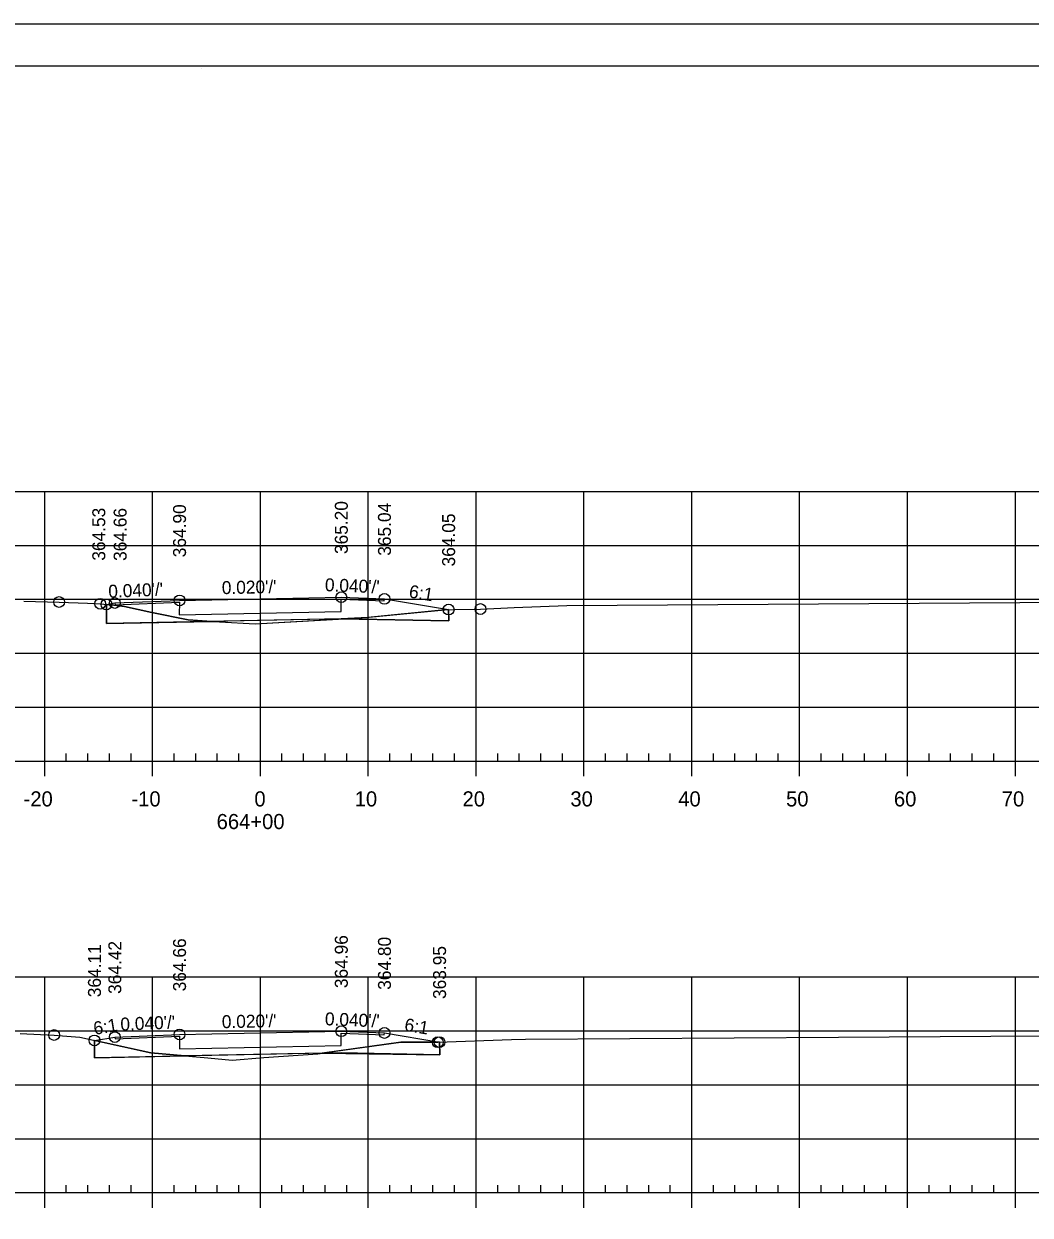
# Model space of a CAD drawing. Extents: x 1359801 to 1362404, y 372415 to 374228.
# Drawn here: x 1361798 to 1361891.3, y 373477.5 to 373588 of the extents above; entities that cross this region are included whole.
import ezdxf

# ---------------------------------------------------------------- set-up
doc = ezdxf.new("R2010")
doc.units = 0
for name, color, linetype in [('S_DRG_PT_SYM', 7, 'Continuous'), ('S_ELECTRIC_UTILITIES_ANNOT', 7, 'Continuous'), ('S_IRON_PIN', 7, 'Continuous'), ('S_MAILBOX', 7, 'Continuous'), ('S_PRIMARY_CTL', 7, 'Continuous'), ('S_SANITARY_SEWER', 7, 'Continuous'), ('S_SHOULDER', 7, 'Continuous'), ('S_UNDERGROUND_CABLE', 7, 'Continuous'), ('S_UTL_PT_SYM', 7, 'Continuous'), ('S_WATER_UTILITIES', 7, 'Continuous')]:
    doc.layers.add(name, color=color, linetype=linetype)

msp = doc.modelspace()

# ---------------------------------------------------------------- linework, layer by layer
at = {"layer": 'S_DRG_PT_SYM'}
for points in [[(1361797.95, 373534.42), (1361801.22, 373534.35), (1361803.85, 373534.24), (1361805.03, 373534.19), (1361806.05, 373534.08), (1361807.28, 373533.92), (1361809.82, 373533.39), (1361813.18, 373532.7), (1361816.09, 373532.51), (1361819.41, 373532.34), (1361829.33, 373532.9), (1361829.84, 373532.93), (1361829.96, 373532.94), (1361837, 373533.64), (1361837.92, 373533.66), (1361840.29, 373533.7), (1361843.42, 373533.83), (1361848.29, 373534.02), (1361890.3, 373534.31), (1361901.28, 373534.38)], [(1361797.62, 373494.35), (1361800.76, 373494.21), (1361801.54, 373494.14), (1361803.15, 373494), (1361804.42, 373493.72), (1361809.74, 373492.55), (1361815.01, 373492.08), (1361817.26, 373491.89), (1361820.2, 373492.11), (1361825.21, 373492.47), (1361826.85, 373492.7), (1361832.9, 373493.55), (1361835.05, 373493.54), (1361836.33, 373493.54), (1361843.17, 373493.79), (1361844.46, 373493.84), (1361873.48, 373494.02), (1361897.03, 373494.17)]]:
    msp.add_lwpolyline(points, dxfattribs=at)
at = {"layer": 'S_ELECTRIC_UTILITIES_ANNOT'}
for p, q in [((1361805.61, 373534.13), (1361805.61, 373532.36)), ((1361837.35, 373532.6), (1361837.34, 373533.65)), ((1361813.18, 373532.7), (1361809.82, 373533.39)), ((1361815.35, 373532.56), (1361815.35, 373532.56)), ((1361815.35, 373532.56), (1361815.35, 373532.56)), ((1361804.5, 373493.71), (1361804.5, 373492.1)), ((1361836.53, 373492.38), (1361836.5, 373493.55)), ((1361804.5, 373492.1), (1361812.88, 373492.27)), ((1361825.61, 373492.53), (1361836.53, 373492.38)), ((1361825.61, 373492.53), (1361825.61, 373492.53))]:
    msp.add_line(p, q, dxfattribs=at)
for points in [[(1361809.82, 373533.39), (1361807.28, 373533.92), (1361806.05, 373534.08), (1361805.61, 373534.13)], [(1361837.34, 373533.65), (1361837, 373533.64), (1361829.84, 373532.93)], [(1361805.61, 373532.36), (1361815.35, 373532.56), (1361813.18, 373532.7)], [(1361815.35, 373532.56), (1361815.35, 373532.56), (1361816.09, 373532.51), (1361819.41, 373532.34), (1361827.51, 373532.8), (1361827.51, 373532.8), (1361815.35, 373532.56)], [(1361829.84, 373532.93), (1361827.39, 373532.8), (1361837.35, 373532.6)], [(1361812.88, 373492.27), (1361809.74, 373492.55), (1361804.5, 373493.71)], [(1361836.5, 373493.55), (1361836.33, 373493.54), (1361835.05, 373493.54), (1361832.9, 373493.55), (1361825.61, 373492.53)], [(1361825.61, 373492.53), (1361812.88, 373492.27), (1361812.88, 373492.27)], [(1361812.88, 373492.27), (1361812.88, 373492.27), (1361815.01, 373492.08), (1361817.26, 373491.89), (1361820.2, 373492.11), (1361825.21, 373492.47), (1361825.61, 373492.53), (1361825.61, 373492.53)]]:
    msp.add_lwpolyline(points, dxfattribs=at)
at = {"layer": 'S_MAILBOX'}
for p, q in [((1361674.89, 373544.6), (1361964.89, 373544.6)), ((1361799.89, 373519.6), (1361799.89, 373544.6)), ((1361809.89, 373519.6), (1361809.89, 373544.6)), ((1361819.89, 373519.6), (1361819.89, 373544.6)), ((1361829.89, 373519.6), (1361829.89, 373544.6)), ((1361839.89, 373519.6), (1361839.89, 373544.6)), ((1361849.89, 373519.6), (1361849.89, 373544.6)), ((1361859.89, 373519.6), (1361859.89, 373544.6)), ((1361869.89, 373519.6), (1361869.89, 373544.6)), ((1361879.89, 373519.6), (1361879.89, 373544.6)), ((1361889.89, 373519.6), (1361889.89, 373544.6)), ((1361674.89, 373539.6), (1361964.89, 373539.6)), ((1361674.89, 373534.6), (1361964.89, 373534.6)), ((1361674.89, 373529.6), (1361964.89, 373529.6)), ((1361674.89, 373524.6), (1361964.89, 373524.6)), ((1361674.89, 373519.6), (1361964.89, 373519.6)), ((1361674.89, 373499.6), (1361964.89, 373499.6)), ((1361799.89, 373479.6), (1361799.89, 373499.6)), ((1361809.89, 373479.6), (1361809.89, 373499.6)), ((1361819.89, 373479.6), (1361819.89, 373499.6)), ((1361829.89, 373479.6), (1361829.89, 373499.6)), ((1361839.89, 373479.6), (1361839.89, 373499.6)), ((1361849.89, 373479.6), (1361849.89, 373499.6)), ((1361859.89, 373479.6), (1361859.89, 373499.6)), ((1361869.89, 373479.6), (1361869.89, 373499.6)), ((1361879.89, 373479.6), (1361879.89, 373499.6)), ((1361889.89, 373479.6), (1361889.89, 373499.6)), ((1361674.89, 373494.6), (1361964.89, 373494.6)), ((1361674.89, 373489.6), (1361964.89, 373489.6)), ((1361674.89, 373484.6), (1361964.89, 373484.6)), ((1361674.89, 373479.6), (1361964.89, 373479.6))]:
    msp.add_line(p, q, dxfattribs=at)
at = {"layer": 'S_SANITARY_SEWER'}
for points in [[(1361805.61, 373534.13), (1361806.39, 373534.26), (1361812.39, 373534.5), (1361812.39, 373534.5), (1361827.39, 373534.8), (1361831.39, 373534.64), (1361837.34, 373533.65)], [(1361804.5, 373493.71), (1361806.39, 373494.02), (1361812.39, 373494.26), (1361812.39, 373494.26), (1361827.39, 373494.56), (1361831.39, 373494.4), (1361836.5, 373493.55)]]:
    msp.add_lwpolyline(points, dxfattribs=at)
at = {"layer": 'S_SHOULDER'}
for p, q in [((1361649.49, 373587.95), (1361982.82, 373587.95)), ((1361805.61, 373532.36), (1361805.61, 373534.13)), ((1361837.34, 373533.65), (1361837.35, 373532.6)), ((1361837.35, 373532.6), (1361837.33, 373532.6)), ((1361804.5, 373492.1), (1361804.5, 373493.71)), ((1361827.39, 373492.56), (1361812.4, 373492.26)), ((1361836.53, 373492.38), (1361827.39, 373492.56)), ((1361836.5, 373493.55), (1361836.53, 373492.38)), ((1361812.4, 373492.26), (1361804.51, 373492.1))]:
    msp.add_line(p, q, dxfattribs=at)
for points in [[(1361649.48, 373587.95), (1361982.82, 373587.95), (1361982.82, 373374.61), (1361649.48, 373374.61)], [(1361895.81, 373584.06), (1361895.81, 373574.18), (1361931.54, 373574.18), (1361931.54, 373571.26), (1361954.74, 373571.26), (1361954.74, 373546.93), (1361978.07, 373546.93), (1361978.07, 373378.6), (1361661.89, 373378.6), (1361661.89, 373584.06)]]:
    msp.add_lwpolyline(points, close=True, dxfattribs=at)
for points in [[(1361812.4, 373534.33), (1361812.37, 373533.17), (1361812.37, 373533.17), (1361827.39, 373533.47), (1361827.39, 373534.63)], [(1361827.39, 373534.63), (1361831.37, 373534.47), (1361831.39, 373534.64), (1361837.34, 373533.65)], [(1361805.61, 373534.13), (1361806.39, 373534.26), (1361806.41, 373534.09), (1361812.4, 373534.33)], [(1361837.33, 373532.6), (1361827.39, 373532.8), (1361805.62, 373532.36)], [(1361804.5, 373493.71), (1361806.39, 373494.02), (1361806.41, 373493.85), (1361812.4, 373494.09)], [(1361812.4, 373494.09), (1361812.39, 373492.93), (1361827.39, 373493.23), (1361827.39, 373494.39)], [(1361827.39, 373494.39), (1361831.37, 373494.23), (1361831.39, 373494.4), (1361836.5, 373493.55)]]:
    msp.add_lwpolyline(points, dxfattribs=at)
for centre in [(1361801.22, 373534.35), (1361805.03, 373534.19), (1361805.61, 373534.13), (1361806.39, 373534.26), (1361812.39, 373534.5), (1361827.39, 373534.8), (1361831.39, 373534.64), (1361837.34, 373533.65), (1361840.29, 373533.7), (1361827.39, 373494.56), (1361831.39, 373494.4), (1361800.76, 373494.21), (1361804.5, 373493.71), (1361806.39, 373494.02), (1361812.39, 373494.26), (1361836.33, 373493.54), (1361836.5, 373493.55)]:
    msp.add_circle(centre, 0.5, dxfattribs=at)
at = {"layer": 'S_UNDERGROUND_CABLE'}
for p, q in [((1361805.61, 373534.13), (1361805.61, 373532.36)), ((1361837.34, 373533.65), (1361837.35, 373532.6)), ((1361804.5, 373493.71), (1361804.5, 373492.1)), ((1361827.39, 373492.56), (1361812.4, 373492.26)), ((1361836.53, 373492.38), (1361827.39, 373492.56)), ((1361836.5, 373493.55), (1361836.53, 373492.38)), ((1361812.4, 373492.26), (1361804.51, 373492.1))]:
    msp.add_line(p, q, dxfattribs=at)
msp.add_lwpolyline([(1361837.33, 373532.6), (1361827.39, 373532.8), (1361805.62, 373532.36)], dxfattribs=at)
at = {"layer": 'S_UTL_PT_SYM'}
for p, q in [((1361661.89, 373584.06), (1361978.07, 373584.06)), ((1361814.41, 373583.8), (1361814.41, 373583.8)), ((1361814.41, 373583.8), (1361814.41, 373583.8))]:
    msp.add_line(p, q, dxfattribs=at)
at = {"layer": 'S_WATER_UTILITIES'}
for p, q in [((1361801.89, 373519.6), (1361801.89, 373520.3)), ((1361803.89, 373519.6), (1361803.89, 373520.3)), ((1361805.89, 373519.6), (1361805.89, 373520.3)), ((1361807.89, 373519.6), (1361807.89, 373520.3)), ((1361811.89, 373519.6), (1361811.89, 373520.3)), ((1361813.89, 373519.6), (1361813.89, 373520.3)), ((1361815.89, 373519.6), (1361815.89, 373520.3)), ((1361817.89, 373519.6), (1361817.89, 373520.3)), ((1361821.89, 373519.6), (1361821.89, 373520.3)), ((1361823.89, 373519.6), (1361823.89, 373520.3)), ((1361825.89, 373519.6), (1361825.89, 373520.3)), ((1361827.89, 373519.6), (1361827.89, 373520.3)), ((1361831.89, 373519.6), (1361831.89, 373520.3)), ((1361833.89, 373519.6), (1361833.89, 373520.3)), ((1361835.89, 373519.6), (1361835.89, 373520.3)), ((1361837.89, 373519.6), (1361837.89, 373520.3)), ((1361841.89, 373519.6), (1361841.89, 373520.3)), ((1361843.89, 373519.6), (1361843.89, 373520.3)), ((1361845.89, 373519.6), (1361845.89, 373520.3)), ((1361847.89, 373519.6), (1361847.89, 373520.3)), ((1361851.89, 373519.6), (1361851.89, 373520.3)), ((1361853.89, 373519.6), (1361853.89, 373520.3)), ((1361855.89, 373519.6), (1361855.89, 373520.3)), ((1361857.89, 373519.6), (1361857.89, 373520.3)), ((1361861.89, 373519.6), (1361861.89, 373520.3)), ((1361863.89, 373519.6), (1361863.89, 373520.3)), ((1361865.89, 373519.6), (1361865.89, 373520.3)), ((1361867.89, 373519.6), (1361867.89, 373520.3)), ((1361871.89, 373519.6), (1361871.89, 373520.3)), ((1361873.89, 373519.6), (1361873.89, 373520.3)), ((1361875.89, 373519.6), (1361875.89, 373520.3)), ((1361877.89, 373519.6), (1361877.89, 373520.3)), ((1361881.89, 373519.6), (1361881.89, 373520.3)), ((1361883.89, 373519.6), (1361883.89, 373520.3)), ((1361885.89, 373519.6), (1361885.89, 373520.3)), ((1361887.89, 373519.6), (1361887.89, 373520.3)), ((1361674.89, 373519.6), (1361964.89, 373519.6)), ((1361799.89, 373518.2), (1361799.89, 373519.6)), ((1361809.89, 373518.2), (1361809.89, 373519.6)), ((1361819.89, 373518.2), (1361819.89, 373519.6)), ((1361829.89, 373518.2), (1361829.89, 373519.6)), ((1361839.89, 373518.2), (1361839.89, 373519.6)), ((1361849.89, 373518.2), (1361849.89, 373519.6)), ((1361859.89, 373518.2), (1361859.89, 373519.6)), ((1361869.89, 373518.2), (1361869.89, 373519.6)), ((1361879.89, 373518.2), (1361879.89, 373519.6)), ((1361889.89, 373518.2), (1361889.89, 373519.6)), ((1361674.89, 373479.6), (1361964.89, 373479.6)), ((1361799.89, 373478.2), (1361799.89, 373479.6)), ((1361801.89, 373479.6), (1361801.89, 373480.3)), ((1361803.89, 373479.6), (1361803.89, 373480.3)), ((1361805.89, 373479.6), (1361805.89, 373480.3)), ((1361807.89, 373479.6), (1361807.89, 373480.3)), ((1361809.89, 373478.2), (1361809.89, 373479.6)), ((1361811.89, 373479.6), (1361811.89, 373480.3)), ((1361813.89, 373479.6), (1361813.89, 373480.3)), ((1361815.89, 373479.6), (1361815.89, 373480.3)), ((1361817.89, 373479.6), (1361817.89, 373480.3)), ((1361819.89, 373478.2), (1361819.89, 373479.6)), ((1361821.89, 373479.6), (1361821.89, 373480.3)), ((1361823.89, 373479.6), (1361823.89, 373480.3)), ((1361825.89, 373479.6), (1361825.89, 373480.3)), ((1361827.89, 373479.6), (1361827.89, 373480.3)), ((1361829.89, 373478.2), (1361829.89, 373479.6)), ((1361831.89, 373479.6), (1361831.89, 373480.3)), ((1361833.89, 373479.6), (1361833.89, 373480.3)), ((1361835.89, 373479.6), (1361835.89, 373480.3)), ((1361837.89, 373479.6), (1361837.89, 373480.3)), ((1361839.89, 373478.2), (1361839.89, 373479.6)), ((1361841.89, 373479.6), (1361841.89, 373480.3)), ((1361843.89, 373479.6), (1361843.89, 373480.3)), ((1361845.89, 373479.6), (1361845.89, 373480.3)), ((1361847.89, 373479.6), (1361847.89, 373480.3)), ((1361849.89, 373478.2), (1361849.89, 373479.6)), ((1361851.89, 373479.6), (1361851.89, 373480.3)), ((1361853.89, 373479.6), (1361853.89, 373480.3)), ((1361855.89, 373479.6), (1361855.89, 373480.3)), ((1361857.89, 373479.6), (1361857.89, 373480.3)), ((1361859.89, 373478.2), (1361859.89, 373479.6)), ((1361861.89, 373479.6), (1361861.89, 373480.3)), ((1361863.89, 373479.6), (1361863.89, 373480.3)), ((1361865.89, 373479.6), (1361865.89, 373480.3)), ((1361867.89, 373479.6), (1361867.89, 373480.3)), ((1361869.89, 373478.2), (1361869.89, 373479.6)), ((1361871.89, 373479.6), (1361871.89, 373480.3)), ((1361873.89, 373479.6), (1361873.89, 373480.3)), ((1361875.89, 373479.6), (1361875.89, 373480.3)), ((1361877.89, 373479.6), (1361877.89, 373480.3)), ((1361879.89, 373478.2), (1361879.89, 373479.6)), ((1361881.89, 373479.6), (1361881.89, 373480.3)), ((1361883.89, 373479.6), (1361883.89, 373480.3)), ((1361885.89, 373479.6), (1361885.89, 373480.3)), ((1361887.89, 373479.6), (1361887.89, 373480.3)), ((1361889.89, 373478.2), (1361889.89, 373479.6))]:
    msp.add_line(p, q, dxfattribs=at)

# ---------------------------------------------------------------- texts
at = {"layer": 'S_IRON_PIN'}
for s, rotation, p in [('365.20', 90, (1361827.99, 373538.8)), ('365.04', 90, (1361831.99, 373538.64)), ('364.53', 90, (1361805.5, 373538.18)), ('364.66', 90, (1361807.48, 373538.16)), ('364.90', 90, (1361812.99, 373538.5)), ('364.05', 90, (1361837.94, 373537.65)), ("0.040'/'", 2.2906, (1361805.81, 373534.74)), ("0.020'/'", 1.1458, (1361816.32, 373535.08)), ("0.040'/'", 357.7094, (1361825.85, 373535.36)), ('6:1', 350.5377, (1361833.6, 373534.78)), ('364.11', 90, (1361805.1, 373497.71)), ('364.42', 90, (1361806.99, 373498.02)), ('364.66', 90, (1361812.99, 373498.26)), ('364.96', 90, (1361827.99, 373498.56)), ('364.80', 90, (1361831.99, 373498.4)), ('363.95', 90, (1361837.1, 373497.55)), ("0.040'/'", 2.2906, (1361806.93, 373494.61)), ("0.020'/'", 1.1458, (1361816.32, 373494.84)), ("0.040'/'", 357.7094, (1361825.85, 373495.12)), ('6:1', 9.4623, (1361804.51, 373494.22)), ('6:1', 350.5377, (1361833.18, 373494.61))]:
    msp.add_text(s, height=1.2, rotation=rotation, dxfattribs=at).set_placement(p)
at = {"layer": 'S_PRIMARY_CTL'}
for s, p in [('-20', (1361797.93, 373515.4)), ('-10', (1361807.93, 373515.4)), ('0', (1361819.33, 373515.4)), ('10', (1361828.63, 373515.4)), ('20', (1361838.63, 373515.4)), ('30', (1361848.63, 373515.4)), ('40', (1361858.63, 373515.4)), ('50', (1361868.63, 373515.4)), ('60', (1361878.63, 373515.4)), ('70', (1361888.63, 373515.4)), ('664+00', (1361815.83, 373513.3))]:
    msp.add_text(s, height=1.4, dxfattribs=at).set_placement(p)
at = {"layer": 'S_SHOULDER'}
for p in [(1361848.24, 373533.97), (1361844.42, 373493.79)]:
    msp.add_text('+', height=0.1, dxfattribs=at).set_placement(p)

doc.saveas('drawing.dxf')
